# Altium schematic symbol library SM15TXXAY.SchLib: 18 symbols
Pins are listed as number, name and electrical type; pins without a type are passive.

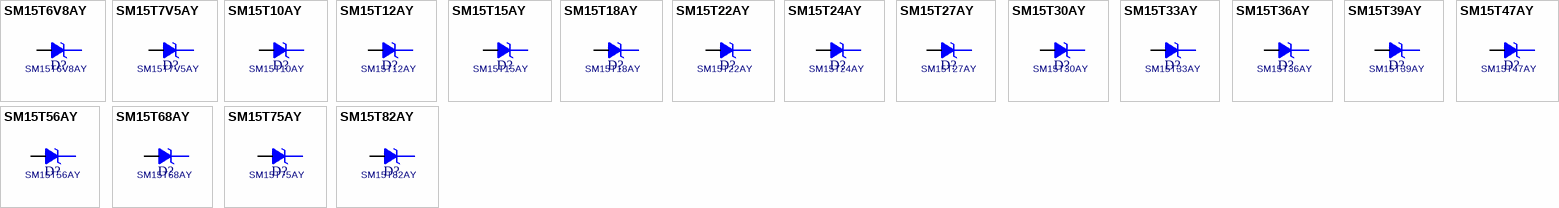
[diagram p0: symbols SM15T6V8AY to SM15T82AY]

## SM15T6V8AY
designator D?
footprint ST_SMC
pins: 1 K, 2 A

## SM15T7V5AY
designator D?
footprint ST_SMC
pins: 1 K, 2 A

## SM15T10AY
designator D?
footprint ST_SMC
pins: 1 K, 2 A

## SM15T12AY
designator D?
footprint ST_SMC
pins: 1 K, 2 A

## SM15T15AY
designator D?
footprint ST_SMC
pins: 1 K, 2 A

## SM15T18AY
designator D?
footprint ST_SMC
pins: 1 K, 2 A

## SM15T22AY
designator D?
footprint ST_SMC
pins: 1 K, 2 A

## SM15T24AY
designator D?
footprint ST_SMC
pins: 1 K, 2 A

## SM15T27AY
designator D?
footprint ST_SMC
pins: 1 K, 2 A

## SM15T30AY
designator D?
footprint ST_SMC
pins: 1 K, 2 A

## SM15T33AY
designator D?
footprint ST_SMC
pins: 1 K, 2 A

## SM15T36AY
designator D?
footprint ST_SMC
pins: 1 K, 2 A

## SM15T39AY
designator D?
footprint ST_SMC
pins: 1 K, 2 A

## SM15T47AY
designator D?
footprint ST_SMC
pins: 1 K, 2 A

## SM15T56AY
designator D?
footprint ST_SMC
pins: 1 K, 2 A

## SM15T68AY
designator D?
footprint ST_SMC
pins: 1 K, 2 A

## SM15T75AY
designator D?
footprint ST_SMC
pins: 1 K, 2 A

## SM15T82AY
designator D?
footprint ST_SMC
pins: 1 K, 2 A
